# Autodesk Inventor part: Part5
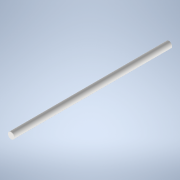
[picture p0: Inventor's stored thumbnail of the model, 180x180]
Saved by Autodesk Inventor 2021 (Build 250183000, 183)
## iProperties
Created: 2021-01
Part Number: Part5
Material: Generic
Document SubType Name: Modeling
Designer: Owner
Density: 1 g/cm^3
Appearance: Default
Mass: 2.11247 g
Surface Area: 17.2924 cm^2
Volume: 2.11247 cm^3
Author: Owner
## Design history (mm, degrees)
sketch "Sketch1"
  geometry: C1 r 2.5 at (-0.567, 6.386); 1 further point
  constraints: 1 centre point
  dimensions: "d0" = 5 diameter of C1
extrude "Extrusion1" new body sketch "Sketch1" distance "d1" = 75; taper "d2" = 0 deg
sketch "Sketch2"
  geometry: C1 r 1.25 at (0, 0); 1 further point
  constraints: 1 centre point
extrude "Extrusion2" join sketch "Sketch2" distance "d3" = 38; taper "d4" = 0 deg
sketch "Sketch3"
  geometry: C1 r 2.5 at (0, 0); 1 further point
  constraints: 1 centre point
extrude "Extrusion3" join sketch "Sketch3" distance "d5" = 40; taper "d6" = 0 deg
sketch "Sketch4"
  geometry: C1 r 2.5 at (0, 0); 1 further point
  constraints: 1 centre point
extrude "Extrusion4" join sketch "Sketch4" distance "d7" = 10; taper "d8" = 0 deg
sketch "Sketch5"
  geometry: C1 r 2.5 at (0, 0); 1 further point
  constraints: 1 centre point
extrude "Extrusion5" cut sketch "Sketch5" distance "d9" = 17.413; taper "d10" = 0 deg
body "Solid1"
